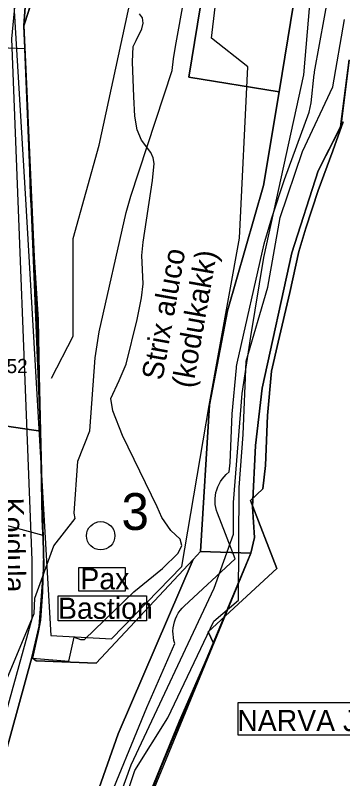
# Model space of a CAD drawing. Extents: x 728832 to 739469, y 6586263 to 6599699.
# Drawn here: x 738766.3 to 738858.8, y 6589739.5 to 6589955.2 of the extents above; entities that cross this region are included whole.
import ezdxf

# ---------------------------------------------------------------- set-up
doc = ezdxf.new("R2010")
doc.units = 0
for name, color, linetype in [('_olol_kinnismalestis', 7, 'Continuous'), ('a_kalda_ekv', 7, 'Continuous'), ('a_kalda_veekaitsev', 7, 'Continuous'), ('a_LK_III_kodukakk', 7, 'Continuous'), ('a_looduskaitse_voond', 7, 'Continuous'), ('a_piir', 7, 'Continuous'), ('a_veekogu_piir', 7, 'Continuous'), ('dp_hoonestus', 7, 'Continuous'), ('plan_ala', 7, 'Continuous'), ('v_dp_kehtiv', 7, 'Continuous'), ('v_dp_kontaktvoond', 7, 'Continuous'), ('v_dp_situatsioon_tekst', 7, 'Continuous'), ('v_dp_tanav_tekst', 7, 'Continuous'), ('v_dp_tekst', 7, 'Continuous'), ('v_olol_hüdrant', 7, 'Continuous'), ('v_olol_transp_jjt', 7, 'Continuous')]:
    doc.layers.add(name, color=color, linetype=linetype)

msp = doc.modelspace()

# ---------------------------------------------------------------- linework, layer by layer
at = {"layer": '_olol_kinnismalestis'}
msp.add_circle((738790.41, 6589808.13), 4, dxfattribs=at)
at = {"layer": 'a_kalda_ekv'}
msp.add_lwpolyline([(738742.89, 6589712.2), (738753.43, 6589742.8), (738771.61, 6589786.21), (738771.76, 6589790.54), (738777.15, 6589805.29), (738783.2, 6589812.99), (738782.87, 6589814.49), (738783.98, 6589829.19), (738787.31, 6589837.75), (738788.85, 6589858.38), (738789.96, 6589865.72), (738797.63, 6589899.49), (738798.92, 6589904.12), (738810.64, 6589939.55), (738811, 6589942.88), (738811.51, 6589946.37), (738821.34, 6590000.5)], dxfattribs=at)
at = {"layer": 'a_kalda_veekaitsev'}
for points in [[(738791.34, 6589730.04), (738803.47, 6589759.65), (738811.37, 6589777.71), (738811.12, 6589778.56), (738810.95, 6589779.43), (738810.85, 6589780.32), (738810.84, 6589781.2), (738810.9, 6589782.09), (738811.04, 6589782.96), (738811.25, 6589783.82), (738811.55, 6589784.66), (738811.91, 6589785.47), (738812.35, 6589786.24), (738812.85, 6589786.98), (738813.41, 6589787.66), (738814.04, 6589788.29), (738828.4, 6589801.59), (738823.41, 6589814.51), (738823.14, 6589815.32), (738822.93, 6589816.14), (738822.8, 6589816.97), (738822.74, 6589817.81), (738822.75, 6589818.66), (738822.83, 6589819.5), (738822.98, 6589820.33), (738823.21, 6589821.15), (738823.49, 6589821.94), (738823.85, 6589822.71), (738824.27, 6589823.44), (738824.75, 6589824.14), (738825.29, 6589824.79), (738825.88, 6589825.4), (738826.69, 6589826.16), (738826.98, 6589828.74), (738827.58, 6589842.58), (738828.75, 6589855.55), (738828.8, 6589855.99), (738828.87, 6589856.43), (738828.96, 6589856.86), (738836.64, 6589890.63), (738836.69, 6589890.85), (738836.75, 6589891.07), (738836.81, 6589891.29), (738838.81, 6589897.96), (738842.36, 6589908.79), (738849.3, 6589927.85), (738849.89, 6589930.49), (738850.77, 6589938.52), (738850.79, 6589938.76), (738850.83, 6589938.99), (738850.87, 6589939.22), (738860.7, 6589993.36)], [(738858.93, 6589925.05), (738855.98, 6589916.9), (738851.86, 6589905.67), (738848.39, 6589895.08), (738846.39, 6589888.41), (738843.87, 6589876.87), (738840.61, 6589862.79), (738838.71, 6589854.64), (738837.57, 6589842.15), (738836.95, 6589827.97), (738836.22, 6589821.4), (738832.74, 6589818.12), (738840.17, 6589798.87), (738820.83, 6589780.95), (738822.32, 6589777.78), (738812.72, 6589755.86), (738800.7, 6589726.52)]]:
    msp.add_lwpolyline(points, dxfattribs=at)
at = {"layer": 'a_LK_III_kodukakk'}
msp.add_lwpolyline([(738774.8, 6589988.29), (738764.14, 6589986.28), (738769.19, 6589903.2), (738776.34, 6589779.97), (738793.46, 6589779), (738813.32, 6589799.46), (738821.04, 6589844.98), (738829.66, 6589892.22), (738832, 6589940.61), (738821.77, 6589948.75), (738824.98, 6589976.65)], close=True, dxfattribs=at)
at = {"layer": 'a_looduskaitse_voond'}
msp.add_lwpolyline([(738783.87, 6590000.64), (738768.64, 6589952.32), (738769.8, 6589927.49), (738770.47, 6589904.48), (738772.78, 6589869.23), (738773.78, 6589812.8), (738773.78, 6589812.8), (738774.27, 6589803.03), (738773.94, 6589792.27), (738773.44, 6589784.33), (738772.78, 6589780.85), (738771.13, 6589773.57), (738781.39, 6589772.74), (738782.88, 6589779.53), (738784.7, 6589778.87), (738785.86, 6589778.87), (738799.76, 6589792.27), (738807.87, 6589798.89), (738812.34, 6589803.2), (738813.33, 6589805.35), (738812.83, 6589807.17), (738810.19, 6589809.65), (738807.7, 6589813.29), (738806.38, 6589816.27), (738796.61, 6589836.46), (738793.8, 6589843.41), (738793.3, 6589846.89), (738795.62, 6589852.02), (738797.61, 6589856.65), (738800.75, 6589869.23), (738801.91, 6589875.36), (738802.41, 6589879.33), (738802.08, 6589887.27), (738802.41, 6589891.08), (738805.06, 6589908.46), (738805.55, 6589913.26), (738805.22, 6589914.91), (738804.56, 6589916.4), (738801.91, 6589919.88), (738800.75, 6589922.86), (738800.09, 6589926.66), (738799.76, 6589932.12), (738799.43, 6589942.05), (738799.59, 6589946.36), (738800.42, 6589948.01), (738802.08, 6589951.32), (738802.41, 6589952.98), (738802.24, 6589954.47), (738801.41, 6589955.63)], dxfattribs=at)
for points in [[(738784.21, 6589799.17), (738797.32, 6589799.17), (738797.32, 6589792.47), (738784.21, 6589792.47)], [(738778.41, 6589791.19), (738803.38, 6589791.19), (738803.38, 6589784.14), (738778.41, 6589784.14)], [(738829.24, 6589761.03), (738872.61, 6589761.03), (738872.61, 6589751.77), (738829.24, 6589751.77)]]:
    msp.add_lwpolyline(points, close=True, dxfattribs=at)
at = {"layer": 'a_piir'}
for points in [[(738742.13, 6590093.07), (738764.49, 6590055.06), (738772.03, 6590000.09), (738768.72, 6589952.16), (738772.93, 6589857.45), (738773.4, 6589837.7), (738774.3, 6589799.69), (738773.02, 6589782.57), (738770.95, 6589773.79), (738772.21, 6589772.82), (738789.1, 6589772.13), (738816.58, 6589801.47), (738818.65, 6589803.67), (738821.12, 6589845.16), (738826.29, 6589871.7), (738836.38, 6589907.12), (738840.89, 6589933.53), (738815.28, 6589937.74), (738820.97, 6589972.38), (738846.51, 6589968.23), (738849.37, 6589989.36), (738833.77, 6589993.69), (738901.84, 6590117.49)], [(738901.84, 6590117.49), (738833.77, 6589993.69), (738849.37, 6589989.36), (738846.51, 6589968.23), (738840.89, 6589933.53), (738836.38, 6589907.12), (738826.29, 6589871.7), (738821.12, 6589845.16), (738818.65, 6589803.67), (738832.86, 6589803.2), (738833.85, 6589807.67), (738833.36, 6589816.28), (738834.18, 6589833.66), (738836, 6589849.88), (738844.44, 6589888.11), (738851.89, 6589911.28), (738858.18, 6589923.69), (738860.66, 6589942.56)], [(738716.96, 6590090.08), (738738.99, 6590049.61), (738748.53, 6590037.67), (738752.27, 6590014.17), (738752.88, 6590000.39), (738757.06, 6589920.61), (738757.14, 6589919.04), (738760.94, 6589844.8), (738761.22, 6589839.49), (738773.4, 6589837.7), (738772.93, 6589857.45), (738768.72, 6589952.16), (738772.03, 6590000.09), (738764.49, 6590055.06), (738742.13, 6590093.07)], [(738746.35, 6589684.41), (738770.95, 6589773.79), (738773.02, 6589782.57), (738774.3, 6589799.69), (738773.4, 6589837.7), (738761.22, 6589839.49), (738761.57, 6589811.73), (738761.83, 6589791.03), (738753.47, 6589756.53), (738744.47, 6589720.57)]]:
    msp.add_lwpolyline(points, dxfattribs=at)
for points in [[(738820.97, 6589972.38), (738815.28, 6589937.74), (738840.89, 6589933.53), (738846.51, 6589968.23)], [(738818.65, 6589803.67), (738816.58, 6589801.47), (738795.34, 6589752.22), (738777.99, 6589702.96), (738758.7, 6589627.88), (738757.14, 6589618.51), (738752.81, 6589592.39), (738751.65, 6589575.27), (738759.03, 6589574.73), (738765.66, 6589574.27), (738765.75, 6589575.1), (738768.64, 6589594.83), (738773.44, 6589613.05), (738791.32, 6589619.33), (738790.82, 6589629.42), (738792.48, 6589655.08), (738789.33, 6589670.8), (738789.33, 6589687.35), (738791.81, 6589703.4), (738807.87, 6589743.62), (738832.86, 6589803.2)], [(738816.58, 6589801.47), (738789.1, 6589772.13), (738772.21, 6589772.82), (738770.95, 6589773.79), (738746.35, 6589684.41), (738743.87, 6589682.99), (738733.85, 6589649.27), (738705.07, 6589616.72), (738695.73, 6589610.51), (738719.2, 6589616.31), (738729.37, 6589618.81), (738757.14, 6589618.51), (738758.7, 6589627.88), (738777.99, 6589702.96), (738795.34, 6589752.22)]]:
    msp.add_lwpolyline(points, close=True, dxfattribs=at)
at = {"layer": 'a_veekogu_piir'}
msp.add_lwpolyline([(738800.7, 6589726.52), (738812.72, 6589755.86), (738822.32, 6589777.78), (738820.83, 6589780.95), (738840.17, 6589798.87), (738832.74, 6589818.12), (738836.22, 6589821.4), (738836.95, 6589827.97), (738837.57, 6589842.15), (738838.71, 6589854.64), (738840.61, 6589862.79), (738843.87, 6589876.87), (738846.39, 6589888.41), (738848.39, 6589895.08), (738851.86, 6589905.67), (738855.98, 6589916.9), (738858.93, 6589925.05)], dxfattribs=at)
at = {"layer": 'dp_hoonestus'}
msp.add_lwpolyline([(738791.32, 6589715.31), (738800.09, 6589741.79), (738809.36, 6589756.69), (738822.43, 6589784), (738829.38, 6589789.96), (738829.55, 6589821.73), (738830.71, 6589836.79), (738831.54, 6589857.48), (738837.66, 6589878.34), (738841.13, 6589898.03), (738847.42, 6589916.73), (738856.03, 6589934.94), (738859.34, 6589953.97)], dxfattribs=at)
msp.add_lwpolyline([(738791.32, 6589715.31), (738800.09, 6589741.79), (738809.36, 6589756.69), (738822.43, 6589784), (738829.38, 6589789.96), (738829.55, 6589821.73), (738830.71, 6589836.79), (738831.54, 6589857.48), (738837.66, 6589878.34), (738841.13, 6589898.03), (738847.42, 6589916.73), (738856.03, 6589934.94), (738859.34, 6589953.97)], dxfattribs=at)
at = {"layer": 'plan_ala'}
msp.add_lwpolyline([(738773.4, 6589837.7), (738586.3, 6589865.2), (738586.3, 6589865.2), (738583.11, 6589865.67), (738577.13, 6589865.85), (738565.7, 6589866.14), (738565.45, 6589885.77), (738564.49, 6589941.05), (738581.9, 6589941.15), (738615.11, 6589942.17), (738650.05, 6589943.32), (738691.27, 6589944.8), (738696.09, 6589944.85), (738713.89, 6589945.13), (738703.51, 6589987.79), (738786.92, 6590008.4), (738768.72, 6589952.16)], close=True, dxfattribs=at)
at = {"layer": 'v_dp_kehtiv'}
msp.add_lwpolyline([(738696.09, 6589944.85), (738697.14, 6589884.98), (738611.71, 6589882.8), (738582.94, 6589882.38), (738570.92, 6589882.05), (738572.64, 6589797.79), (738583.56, 6589797.78), (738610.5, 6589797.85), (738634.41, 6589797.92), (738645.6, 6589795.94), (738724.38, 6589781.99), (738735.47, 6589818.89), (738761.57, 6589811.73), (738774.1, 6589808.27), (738773.4, 6589837.7), (738768.98, 6589945.74), (738713.21, 6589947.93), (738713.89, 6589945.13)], close=True, dxfattribs=at)
msp.add_lwpolyline([(738696.09, 6589944.85), (738697.14, 6589884.98), (738611.71, 6589882.8), (738582.94, 6589882.38), (738570.92, 6589882.05), (738572.64, 6589797.79), (738583.56, 6589797.78), (738610.5, 6589797.85), (738634.41, 6589797.92), (738645.6, 6589795.94), (738724.38, 6589781.99), (738735.47, 6589818.89), (738761.57, 6589811.73), (738774.1, 6589808.27), (738773.4, 6589837.7), (738768.98, 6589945.74), (738713.21, 6589947.93), (738713.89, 6589945.13)], close=True, dxfattribs=at)
at = {"layer": 'v_dp_kontaktvoond'}
msp.add_lwpolyline([(738860.63, 6589942.5), (738858.24, 6589923.73), (738851.89, 6589911.28), (738844.44, 6589888.11), (738836, 6589849.88), (738834.18, 6589833.66), (738833.36, 6589816.28), (738833.85, 6589807.67), (738832.86, 6589803.2), (738791.81, 6589703.4), (738790.18, 6589692.87), (738733.43, 6589708.28), (738715.91, 6589709.94), (738675.26, 6589720.49), (738622.28, 6589724.29), (738523.83, 6589724.98), (738508.21, 6589721.7), (738451.79, 6589709.85), (738400.07, 6589688.32)], dxfattribs=at)
at = {"layer": 'v_olol_transp_jjt'}
for points in [[(738701.22, 6589304.96), (738722.43, 6589361.21), (738744.16, 6589429.66), (738746.01, 6589438.06), (738752.32, 6589484.93), (738757.68, 6589561.53), (738761.22, 6589598.39), (738763.23, 6589614.26), (738774.35, 6589665.72), (738786.24, 6589707.98), (738799.01, 6589743.38), (738822.48, 6589793.3), (738827.95, 6589808.63), (738827.95, 6589817.5), (738830.43, 6589848.34), (738832.8, 6589864.39), (738836.51, 6589886.76), (738847.81, 6589938.4), (738851.48, 6589981.51), (738853.67, 6590001.03), (738860.07, 6590020.16), (738885.77, 6590065.05), (738912.97, 6590120.99)], [(738739.83, 6590092.1), (738762.58, 6590052.49), (738765.8, 6590018.73), (738770.03, 6589999.23), (738765.16, 6589948.51), (738770.96, 6589801.22), (738770.96, 6589784.65), (738744.05, 6589687.94), (738732.19, 6589650.65), (738704.24, 6589618.95), (738677.81, 6589602.35), (738554.06, 6589547.05), (738495.74, 6589520.07)], [(738776.52, 6589852.7), (738782.59, 6589864.56), (738782.59, 6589892.11), (738789.97, 6589918.46), (738800.13, 6589965.6), (738807.22, 6589984.64), (738826.43, 6589989.41), (738850.55, 6589997.43)]]:
    msp.add_lwpolyline(points, dxfattribs=at)

# ---------------------------------------------------------------- texts
at = {"layer": '_olol_kinnismalestis'}
msp.add_text('3', height=10.4, dxfattribs=at).set_placement((738796.3, 6589809.78))
at = {"layer": 'v_dp_situatsioon_tekst'}
for s, p in [('Pax', (738784.67, 6589792.99)), ('Bastion', (738778.35, 6589784.67)), ('NARVA JÕGI', (738829.02, 6589752.94))]:
    msp.add_text(s, height=6, dxfattribs=at).set_placement(p)
at = {"layer": 'v_dp_tanav_tekst'}
msp.add_text('Koidula', height=6, rotation=271.185, dxfattribs=at).set_placement((738762.62, 6589818.83))
at = {"layer": 'v_dp_tekst'}
for s, p in [('Strix aluco ', (738807.84, 6589851.84)), ('(kodukakk)', (738816.45, 6589849.61))]:
    msp.add_text(s, height=6, rotation=79.9358, dxfattribs=at).set_placement(p)
at = {"layer": 'v_olol_hüdrant'}
msp.add_text('nr 52', height=4, dxfattribs=at).set_placement((738757.57, 6589854.08))

doc.saveas('drawing.dxf')
